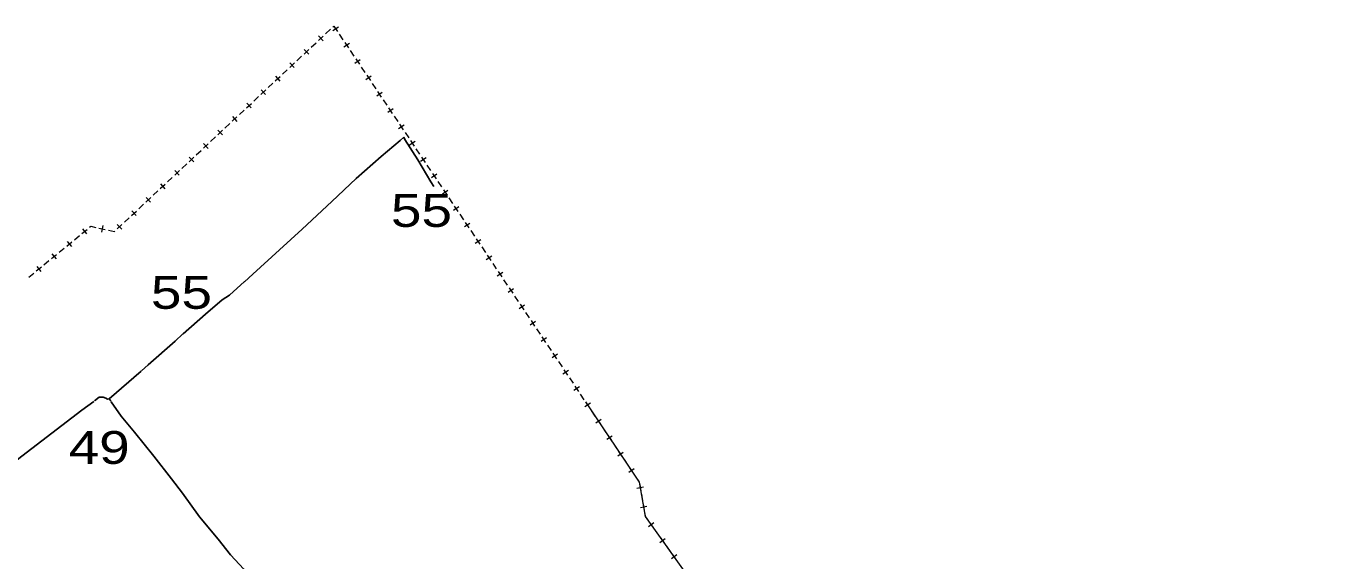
# Model space of a CAD drawing. Extents: x 476989 to 498418, y 4381813 to 4416555.
# Drawn here: x 485670 to 487660, y 4388513 to 4389328 of the extents above; entities that cross this region are included whole.
import ezdxf
from ezdxf.enums import TextEntityAlignment as Align

# ---------------------------------------------------------------- set-up
doc = ezdxf.new("R2010")
doc.units = 0
doc.header["$LTSCALE"] = 20
for name, color, linetype, lineweight in [('13', 7, 'Continuous', 13), ('34', 7, 'Continuous', 13), ('6', 7, 'Continuous', 25)]:
    doc.layers.add(name, color=color, linetype=linetype, lineweight=lineweight)

msp = doc.modelspace()

# ---------------------------------------------------------------- linework, layer by layer
at = {"layer": '34'}
for p, q in [((486136.45, 4389326.54), (486138, 4389328)), ((486138, 4389328), (486143.56, 4389319.7)), ((486114.56, 4389306.04), (486121.86, 4389312.87)), ((486114.79, 4389313.1), (486121.63, 4389305.81)), ((486125.51, 4389316.29), (486132.81, 4389323.13)), ((486144.93, 4389326.63), (486136.62, 4389321.07)), ((486146.34, 4389315.54), (486151.9, 4389307.23)), ((486092.68, 4389285.53), (486099.98, 4389292.37)), ((486092.91, 4389292.6), (486099.75, 4389285.3)), ((486103.63, 4389295.79), (486110.92, 4389302.62)), ((486161.61, 4389301.71), (486153.3, 4389296.15)), ((486154.67, 4389303.08), (486160.23, 4389294.77)), ((486163.01, 4389290.62), (486168.57, 4389282.3)), ((486070.8, 4389265.02), (486078.09, 4389271.86)), ((486071.03, 4389272.09), (486077.86, 4389264.79)), ((486081.74, 4389275.28), (486089.04, 4389282.12)), ((486178.28, 4389276.78), (486169.97, 4389271.22)), ((486171.35, 4389278.16), (486176.91, 4389269.85)), ((486048.91, 4389244.52), (486056.21, 4389251.35)), ((486049.14, 4389251.58), (486055.98, 4389244.29)), ((486059.86, 4389254.77), (486067.16, 4389261.61)), ((486179.69, 4389265.69), (486185.25, 4389257.38)), ((486194.96, 4389251.86), (486186.65, 4389246.3)), ((486188.02, 4389253.23), (486193.59, 4389244.92)), ((486027.03, 4389224.01), (486034.33, 4389230.85)), ((486027.26, 4389231.08), (486034.1, 4389223.78)), ((486037.98, 4389234.27), (486045.27, 4389241.1)), ((486196.37, 4389240.76), (486201.93, 4389232.45)), ((486005.15, 4389203.5), (486012.45, 4389210.34)), ((486005.38, 4389210.57), (486012.22, 4389203.27)), ((486016.09, 4389213.76), (486023.39, 4389220.6)), ((486211.64, 4389226.93), (486203.33, 4389221.37)), ((486204.7, 4389228.31), (486210.26, 4389219.99)), ((486213.04, 4389215.84), (486218.6, 4389207.53)), ((485983.27, 4389182.99), (485990.56, 4389189.83)), ((485983.5, 4389190.06), (485990.33, 4389182.77)), ((485994.21, 4389193.25), (486001.51, 4389200.09)), ((486228.31, 4389202.01), (486220, 4389196.44)), ((486221.38, 4389203.38), (486226.94, 4389195.07)), ((486229.72, 4389190.91), (486235.28, 4389182.6)), ((485961.38, 4389162.49), (485968.68, 4389169.33)), ((485961.61, 4389169.55), (485968.45, 4389162.26)), ((485972.33, 4389172.74), (485979.62, 4389179.58)), ((486244.99, 4389177.08), (486236.68, 4389171.52)), ((486238.06, 4389178.45), (486243.62, 4389170.14)), ((485939.5, 4389141.98), (485946.8, 4389148.82)), ((485939.73, 4389149.05), (485946.57, 4389141.75)), ((485950.45, 4389152.24), (485957.74, 4389159.08)), ((486246.4, 4389165.99), (486251.96, 4389157.68)), ((486261.67, 4389152.15), (486253.36, 4389146.59)), ((486254.73, 4389153.53), (486260.29, 4389145.22)), ((485928.56, 4389131.73), (485935.86, 4389138.57)), ((486263.07, 4389141.06), (486268.63, 4389132.75)), ((485906.68, 4389111.22), (485913.98, 4389118.06)), ((485917.62, 4389121.47), (485924.91, 4389128.31)), ((485917.85, 4389128.54), (485924.68, 4389121.24)), ((486278.35, 4389127.23), (486270.03, 4389121.67)), ((486271.41, 4389128.6), (486276.97, 4389120.29)), ((486279.75, 4389116.14), (486285.31, 4389107.83)), ((485884.8, 4389090.72), (485892.09, 4389097.55)), ((485895.73, 4389100.97), (485903.03, 4389107.8)), ((485895.96, 4389108.03), (485902.8, 4389100.74)), ((486295.02, 4389102.3), (486286.71, 4389096.74)), ((486288.09, 4389103.68), (486293.65, 4389095.37)), ((486296.43, 4389091.21), (486301.99, 4389082.9)), ((485862.91, 4389070.21), (485870.21, 4389077.05)), ((485873.85, 4389080.46), (485881.15, 4389087.3)), ((485874.08, 4389087.53), (485880.92, 4389080.23)), ((486311.7, 4389077.38), (486303.39, 4389071.82)), ((486304.76, 4389078.75), (486310.32, 4389070.44)), ((485841.03, 4389049.7), (485848.33, 4389056.54)), ((485851.97, 4389059.95), (485859.27, 4389066.79)), ((485852.2, 4389067.02), (485859.04, 4389059.72)), ((486313.1, 4389066.29), (486318.66, 4389057.97)), ((486328.38, 4389052.45), (486320.06, 4389046.89)), ((486321.44, 4389053.83), (486327, 4389045.52)), ((485819.15, 4389029.2), (485826.44, 4389036.03)), ((485830.09, 4389039.45), (485837.38, 4389046.28)), ((485830.31, 4389046.51), (485837.15, 4389039.22)), ((486329.78, 4389041.36), (486335.34, 4389033.05)), ((485754.59, 4389012), (485762.32, 4389018.34)), ((485755.29, 4389019.04), (485761.63, 4389011.31)), ((485780.35, 4389020.26), (485790.11, 4389018.09)), ((485786.31, 4389024.05), (485784.14, 4389014.29)), ((485808.2, 4389018.94), (485815.5, 4389025.78)), ((485808.43, 4389026.01), (485815.27, 4389018.71)), ((486345.05, 4389027.53), (486336.74, 4389021.97)), ((486338.12, 4389028.9), (486343.68, 4389020.59)), ((486346.46, 4389016.43), (486352.02, 4389008.12)), ((485719.82, 4388983.46), (485727.55, 4388989.81)), ((485731.41, 4388992.97), (485739.14, 4388999.32)), ((485732.1, 4389000.01), (485738.45, 4388992.28)), ((485743.01, 4389002.49), (485750.74, 4389008.83)), ((486361.73, 4389002.6), (486353.42, 4388997.04)), ((486354.79, 4389003.98), (486360.35, 4388995.66)), ((486363.13, 4388991.51), (486368.7, 4388983.2)), ((485696.64, 4388964.44), (485704.37, 4388970.78)), ((485708.23, 4388973.95), (485715.96, 4388980.29)), ((485708.92, 4388980.98), (485715.27, 4388973.25)), ((486378.41, 4388977.68), (486370.09, 4388972.11)), ((486371.47, 4388979.05), (486377.03, 4388970.74)), ((485673.46, 4388945.41), (485681.19, 4388951.76)), ((485685.05, 4388954.92), (485692.78, 4388961.27)), ((485685.74, 4388961.96), (485692.08, 4388954.23)), ((486379.81, 4388966.58), (486385.37, 4388958.27)), ((486395.08, 4388952.75), (486386.77, 4388947.19)), ((486388.15, 4388954.12), (486393.71, 4388945.81)), ((486396.49, 4388941.66), (486402.05, 4388933.35)), ((486411.76, 4388927.82), (486403.45, 4388922.26)), ((486404.82, 4388929.2), (486410.38, 4388920.89)), ((486413.16, 4388916.73), (486418.73, 4388908.42)), ((486428.44, 4388902.9), (486420.13, 4388897.34)), ((486421.5, 4388904.27), (486427.06, 4388895.96)), ((486429.84, 4388891.81), (486435.4, 4388883.5)), ((486445.11, 4388877.97), (486436.8, 4388872.41)), ((486438.18, 4388879.35), (486443.74, 4388871.04)), ((486446.52, 4388866.88), (486452.08, 4388858.57)), ((486461.79, 4388853.05), (486453.48, 4388847.49)), ((486454.85, 4388854.42), (486460.41, 4388846.11)), ((486463.2, 4388841.96), (486468.76, 4388833.64)), ((486478.47, 4388828.12), (486470.16, 4388822.56)), ((486471.53, 4388829.5), (486477.09, 4388821.19)), ((486479.87, 4388817.03), (486485.43, 4388808.72)), ((486495.14, 4388803.2), (486486.83, 4388797.64)), ((486488.21, 4388804.57), (486493.77, 4388796.26)), ((486496.55, 4388792.1), (486502.11, 4388783.79)), ((486511.82, 4388778.27), (486503.51, 4388772.71)), ((486504.88, 4388779.65), (486510.45, 4388771.33)), ((486513.23, 4388767.18), (486518.79, 4388758.87)), ((486528.5, 4388753.35), (486520.19, 4388747.78)), ((486521.56, 4388754.72), (486527.12, 4388746.41)), ((486529.9, 4388742.25), (486535.46, 4388733.94)), ((486545.17, 4388728.42), (486536.86, 4388722.86)), ((486538.24, 4388729.79), (486543.8, 4388721.48)), ((486546.58, 4388717.33), (486552.14, 4388709.02)), ((486561.85, 4388703.49), (486553.54, 4388697.93)), ((486554.91, 4388704.87), (486560.48, 4388696.56)), ((486563.26, 4388692.4), (486568.82, 4388684.09)), ((486578.53, 4388678.57), (486570.22, 4388673.01)), ((486571.59, 4388679.94), (486577.15, 4388671.63)), ((486579.93, 4388667.48), (486585.49, 4388659.17)), ((486595.2, 4388653.64), (486586.89, 4388648.08)), ((486588.27, 4388655.02), (486593.83, 4388646.71)), ((486596.61, 4388642.55), (486602.17, 4388634.24)), ((486609.38, 4388625.48), (486599.52, 4388623.77)), ((486603.6, 4388629.55), (486605.3, 4388619.7)), ((486606.15, 4388614.77), (486607.86, 4388604.92)), ((486614.49, 4388595.93), (486604.64, 4388594.22)), ((486608.71, 4388600), (486610.42, 4388590.15)), ((486618.21, 4388572.28), (486624.02, 4388564.14)), ((486625.19, 4388571.11), (486617.04, 4388565.31)), ((486626.92, 4388560.07), (486632.72, 4388551.92)), ((486642.59, 4388546.69), (486634.45, 4388540.89)), ((486635.62, 4388547.86), (486641.42, 4388539.72)), ((486644.33, 4388535.65), (486650.13, 4388527.5)), ((486660, 4388522.27), (486651.86, 4388516.47)), ((486653.03, 4388523.44), (486658.83, 4388515.3))]:
    msp.add_line(p, q, dxfattribs=at)
for points in [[(485766.19, 4389021.51), (485768, 4389023), (485775.48, 4389021.34)], [(485794.99, 4389017), (485804, 4389015), (485804.56, 4389015.53)], [(486520.9, 4388755.72), (486603, 4388633), (486612, 4388581), (486746, 4388393), (486776, 4388338), (486812, 4388290), (486879, 4388250), (487017, 4388189), (487152, 4388148), (487234, 4388140), (487360, 4387899), (487497, 4387717), (487531, 4387660), (487608, 4387440), (487634, 4387181), (487675, 4387065), (487547, 4387001), (487350, 4386921), (487175, 4386900), (487110, 4386912), (487380, 4386493), (487280.6, 4386441.97)], [(486611.27, 4388585.22), (486612, 4388581), (486615.32, 4388576.35)]]:
    msp.add_lwpolyline(points, dxfattribs=at)
at = {"layer": '6'}
for p, q in [((485796.06, 4388760.1), (485844.58, 4388802.43)), ((485796.2, 4388760.11), (485798.58, 4388757.09))]:
    msp.add_line(p, q, dxfattribs=at)
for points in [[(486001.93, 4388938.61), (486014.55, 4388950.06), (486055.52, 4388987.26), (486089.93, 4389018.56), (486134.81, 4389061.03), (486172.22, 4389095.85), (486209.9, 4389129.16), (486238.99, 4389153.84), (486244.36, 4389158.81)], [(486244.36, 4389158.81), (486246.3, 4389155.36), (486266.08, 4389124.41), (486285.79, 4389090.61), (486290.28, 4389083.44)], [(485908.72, 4388859.13), (485942.82, 4388889.38), (485967.78, 4388911.23), (485979.12, 4388917.87), (486002.07, 4388938.75)], [(485845.07, 4388802.86), (485855.41, 4388811.97), (485896.23, 4388848.05), (485908.32, 4388858.96)], [(485556.22, 4388588.91), (485598.98, 4388622.45), (485662.95, 4388672.73), (485708.55, 4388708.04), (485754.62, 4388742.62), (485772.47, 4388756.23)], [(485773.67, 4388757.14), (485780.73, 4388762.52), (485783.72, 4388762.91), (485786.72, 4388762.91), (485790.86, 4388761.38), (485793.38, 4388759.69), (485796.06, 4388760.1)], [(485799.02, 4388756.18), (485799.28, 4388755.64), (485814.2, 4388733.49), (485834.73, 4388709.28), (485864.11, 4388672.95), (485890.94, 4388638.49), (485907.48, 4388616.48), (485933.57, 4388580.5), (485961.99, 4388546.41), (485980.86, 4388522.5), (486000.92, 4388500.56), (486016.79, 4388478.01), (486033.78, 4388459.37)]]:
    msp.add_lwpolyline(points, dxfattribs=at)

# ---------------------------------------------------------------- texts
at = {"layer": '13', "width": 1.25}
for p in [(486271.45, 4389022.13), (485906.05, 4388897.3)]:
    msp.add_text('55', height=50, dxfattribs=at).set_placement(p, align=Align.CENTER)
at = {"layer": '6', "width": 1.25}
msp.add_text('49', height=50, dxfattribs=at).set_placement((485780.75, 4388661), align=Align.CENTER)

doc.saveas('drawing.dxf')
